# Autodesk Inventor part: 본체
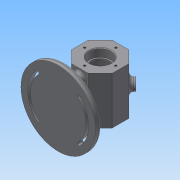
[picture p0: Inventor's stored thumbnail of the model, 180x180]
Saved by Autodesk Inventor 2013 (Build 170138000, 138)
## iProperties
Created: 2017-06
Part Number: 본체
Material: 일반
Document SubType Name: Modeling
Designer: Administrator
Density: 1 g/cm^3
Author: Administrator
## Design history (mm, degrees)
sketch "스케치1" dims "d0" = 60
  geometry: L1 (-12.426, -30)-(-30, -12.426); L2 (-30, -12.426)-(-30, 12.426); L3 (-30, 12.426)-(-12.426, 30); L4 (-12.426, 30)-(12.426, 30); L5 (12.426, 30)-(30, 12.426); L6 (30, 12.426)-(30, -12.426); L7 (30, -12.426)-(12.426, -30); L8 (12.426, -30)-(-12.426, -30); 4 further points
  constraints: 16 end point, 2 coincident, 1 midpoint, 1 vertical alignment, 19 other
extrude "돌출1" new body sketch "스케치1" stored distance "d1" = 70; taper "d2" = 0 deg
sketch "스케치2"
  geometry: L1 (0, 35)-(0, -35); L2 (0, -35)-(16, -35); L3 (16, -35)-(16, -23); L4 (16, -23)-(14, -23); L5 (14, -23)-(14, -20); L6 (14, -20)-(25, -20); L7 (25, -20)-(25, 20); L8 (25, 20)-(14, 20); L9 (14, 20)-(14, 23); L10 (14, 23)-(16, 23); L11 (16, 23)-(16, 35); L12 (16, 35)-(0, 35); 2 further points
  constraints: 24 end point, 6 parallel, 5 perpendicular, 4 equal length, 1 coincident, 1 midpoint, 1 vertical
  dimensions: "d3" = 50 diameter of L7 L1; "d5" = 28 diameter of L5 L1; "d6" = 32 diameter of L3 L1; "d8" = 3 distance of L4.end L5.end; "d9" = 12 distance of L2.end L3.end; "d10" = 40 distance of L6.end L7.end
revolve "회전1" sketch "스케치2" stored, may be unused: angle "d11" = 90 deg
node "작업 평면1"
sketch "스케치3"
  geometry: C1 r 55 at (0, 0); 1 further point
  constraints: 1 centre point, 1 coincident
  dimensions: "d13" = 110 diameter of C1
extrude "돌출2" join sketch "스케치3" distance "d14" = 10; taper "d15" = 0 deg
sketch "스케치4"
  geometry: L1 (0, 0)-(-30.406, -30.406); L2 (0, 0)-(43, 0); L3 (0, 0)-(-30.406, 30.406); C1 r 55 at (0, 0) reference; A1 r 48 centre (0, 0) between (-33.941, 33.941) and (-33.941, -33.941); A2 r 38 centre (0, 0) between (-26.87, 26.87) and (-26.87, -26.87); A3 r 5 centre (-30.406, -30.406) between (-33.941, -33.941) and (-26.87, -26.87); A4 r 5 centre (-30.406, 30.406) between (-26.87, 26.87) and (-33.941, 33.941)
  constraints: 8 point on circle, 6 end point, 5 coincident, 4 centre point, 1 equal length, 1 horizontal, 1 perpendicular
  dimensions: "d16" = 96 diameter of A1; "d17" = 76 diameter of A2; "d18" = 43 distance of L1.start L1.end; "d19" = 135 deg angle of L1 L2; "d20" = 43 distance of L1.start L3.end; "d21" = 10 diameter of A3; "d22" = 10 diameter of A4
extrude "돌출3" cut sketch "스케치4" distance "d23" = 3; taper "d24" = 0 deg
sketch "스케치5"
  geometry: A1 r 38 centre (0, 0) between (-26.87, 26.87) and (-26.87, -26.87) reference; A2 r 5 centre (-30.406, 30.406) between (-26.87, 26.87) and (-33.941, 33.941) reference; A3 r 48 centre (0, 0) between (-33.941, 33.941) and (-33.941, -33.941) reference; A4 r 5 centre (-30.406, -30.406) between (-33.941, -33.941) and (-26.87, -26.87) reference; A5 r 2 centre (-30.406, 30.406) between (-28.991, 28.991) and (-31.82, 31.82); A6 r 41 centre (0, 0) between (-28.991, 28.991) and (-28.991, -28.991); A7 r 2 centre (-30.406, -30.406) between (-31.82, -31.82) and (-28.991, -28.991); A8 r 45 centre (0, 0) between (-31.82, 31.82) and (-31.82, -31.82)
  constraints: 8 point on circle, 4 centre point, 3 other
  dimensions: "d25" = 2 radius of A5
extrude "돌출4" cut sketch "스케치5" stored distance "d27" = 3; taper "d28" = 0 deg
sketch "스케치6"
  geometry: L1 (-5, -24)-(5, -24); L2 (5, -24)-(5, 24); L3 (5, 24)-(-5, 24); L4 (-5, 24)-(-5, -24); L5 (-5, -24)-(5, 24); L6 (5, -24)-(-5, 24); C1 r 55 at (0, 0) reference; C2 r 5 at (0, 24); C3 r 5 at (0, -24)
  constraints: 12 end point, 4 midpoint, 2 centre point, 2 parallel, 1 horizontal, 1 perpendicular
  dimensions: "d29" = 10 distance of L3.end L2.end; "d30" = 48 distance of L2.end L1.end; "d31" = 10 diameter of C2; "d32" = 10 diameter of C3
extrude "돌출5" join sketch "스케치6" stored distance "d33" = 3; taper "d34" = 0 deg
sketch "스케치7"
  geometry: L1 (0, 0)-(26.163, 26.163); L2 (0, 0)-(37, 0)
  constraints: 4 end point, 1 equal length, 1 horizontal
  dimensions: "d35" = 37 distance of L1.start L1.end; "d36" = 45 deg angle of L2 L1
node "작업 평면2"
sketch "스케치8"
  geometry: C1 r 8 at (0, 0); 1 further point
  constraints: 1 centre point, 1 coincident
  dimensions: "d37" = 16 diameter of C1
extrude "돌출6" join sketch "스케치8" stored distance "d38" = 3; taper "d39" = 0 deg
hole "구멍1" diameter "d42" = 8; stored, may be unused: countersink angle "d46" = 90 deg, drill point angle "d48" = 118 deg; dims "d40" = 10, "d41" = 10, "d43" = 6, "d44" = 4, "d45" = 2, "d47" = 8
sketch "스케치9"
  geometry: C1 r 16 at (0, 0) reference; 1 further point
  constraints: 1 vertical alignment
  dimensions: "d49" = 23 distance of C1.centre point (0, 23)
hole "구멍2" sketch "스케치9" at (0, 23) diameter "d50" = 3.242; stored, may be unused: countersink angle "d54" = 90 deg, drill point angle "d56" = 118 deg; dims "d51" = 8, "d52" = 4, "d53" = 2, "d55" = 10
fillet "모깎기1" dims "d60" = 1, "d61" = 5, "d62" = 5
fillet "모깎기2" dims "d63" = 3, "d64" = 0.3
chamfer "모따기1" distance "d65" = 1; stored, may be unused: second distance "d66" = 2, angle "d67" = 45 deg
sketch "스케치10"
  geometry: L1 (24.024, 0)-(0, 0) reference; 2 further points
  constraints: 1 coincident, 1 other
  dimensions: "d68" = 35 distance from line of L1 point (12.012, 35)
feature "엠보싱1" sketch "스케치10" dims "d3" = 50, "d5" = 28, "d6" = 32, "d8" = 3, "d9" = 12, "d10" = 40, "d69" = 0.5, "d70" = 0
node "솔리드1"
mirror "대칭1"
pattern_circular "원형 패턴1" dims angle "d58" = 360 deg
mirror "대칭2"
other parameters: "d12" = -62
